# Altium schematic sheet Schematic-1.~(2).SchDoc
size A4; SheetNumber: 1; SheetTotal: 1
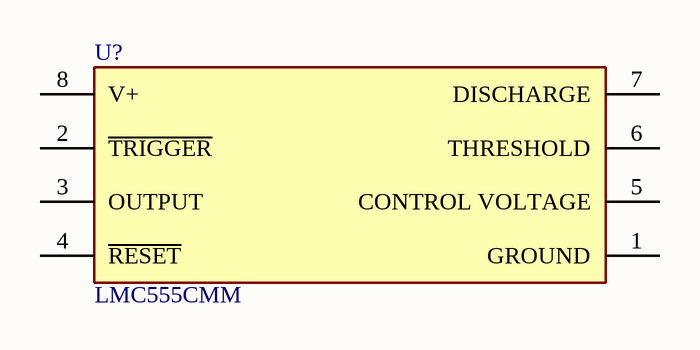
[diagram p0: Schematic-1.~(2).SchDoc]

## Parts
U?  LMC555CMM  [FP-DGK0008A-MFG]

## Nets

Not connected (* = marked no-connect by the designer): U? 1(GROUND) 2(~{TRIGGER}) 3(OUTPUT) 4(~{RESET}) 5(CONTROL_VOLTAGE) 6(THRESHOLD) 7(DISCHARGE) 8(V+)

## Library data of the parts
U? = CMP-0056-00151-4: Manufacturer Lifecycle Status: NRND; NexarPartId: 24849346; Frequency: 3MHz; Number of Channels: 1; Max Power Dissipation: 555mW; Turn-On Delay Time: 100ns; Min Supply Voltage: 1.5V; Max Supply Voltage: 15V; High Level Output Current: -10mA; Nominal Supply Current: 50µA; Operating Supply Current: 150µA; Low Level Output Current: 50mA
